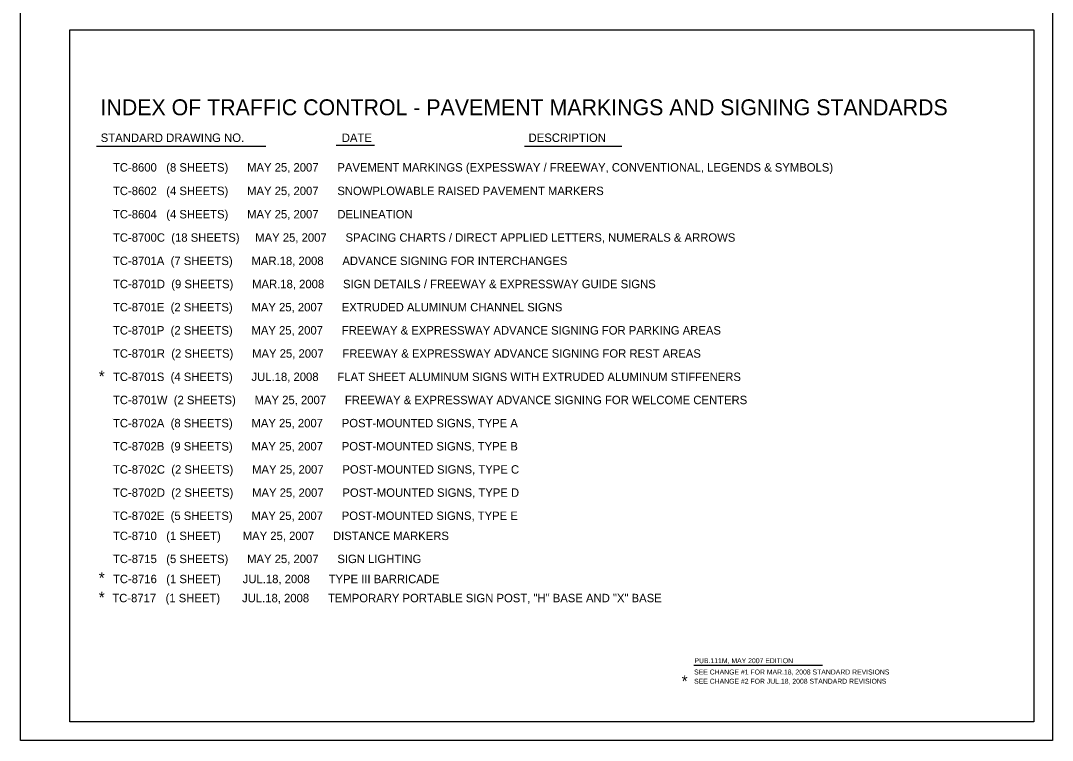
# Model space of a CAD drawing. Extents: x -1746 to -905, y 22 to 1210.
# Drawn here: x -1746 to -905, y 22 to 609 of the extents above; entities that cross this region are included whole.
import ezdxf

# ---------------------------------------------------------------- set-up
doc = ezdxf.new("R2010")
doc.units = 0
for name, color, linetype in [('1', 7, 'Continuous'), ('Level 1', 7, 'Continuous'), ('Level 2', 7, 'Continuous'), ('PLT-BNDY', 7, 'Continuous')]:
    doc.layers.add(name, color=color, linetype=linetype)

msp = doc.modelspace()

# ---------------------------------------------------------------- linework, layer by layer
at = {"layer": '1'}
msp.add_line((-1197.52, 83.48), (-1092.44, 83.48), dxfattribs=at)
at = {"layer": 'Level 1'}
for p, q in [((-1706.14, 601.17), (-920.14, 601.17)), ((-1706.14, 37.17), (-1706.14, 601.17)), ((-920.14, 601.17), (-920.14, 37.17)), ((-920.14, 37.17), (-1706.14, 37.17))]:
    msp.add_line(p, q, dxfattribs=at)
at = {"layer": 'Level 2'}
for p, q in [((-1684.39, 506.28), (-1546.27, 506.28)), ((-1488.89, 507.28), (-1457.77, 507.28)), ((-1335.52, 506.28), (-1256.14, 506.28)), ((-1670.89, 492.53), (-1670.89, 492.53)), ((-1670.89, 454.38), (-1670.89, 454.38)), ((-1670.89, 435.38), (-1670.89, 435.38)), ((-1670.89, 416.5), (-1670.89, 416.5)), ((-1670.89, 359.75), (-1670.89, 359.75)), ((-1670.89, 340.88), (-1670.89, 340.88)), ((-1670.89, 284.25), (-1670.89, 284.25)), ((-1670.89, 265.25), (-1670.89, 265.25)), ((-1670.89, 246.38), (-1670.89, 246.38)), ((-1670.89, 227.5), (-1670.89, 227.5)), ((-1670.89, 208.63), (-1670.89, 208.63)), ((-1670.89, 173.5), (-1670.89, 173.5))]:
    msp.add_line(p, q, dxfattribs=at)
at = {"layer": 'PLT-BNDY'}
msp.add_lwpolyline([(-1746.14, 616.17), (-905.14, 616.17), (-905.14, 22.17), (-1746.14, 22.17)], close=True, dxfattribs=at)

# ---------------------------------------------------------------- texts
at = {"layer": '1'}
for s, height, p in [('*', 9.32, (-1682.48, 314.17)), ('*', 9.32, (-1682.48, 149.9)), ('*', 9.32, (-1682.48, 133.99)), ('PUB.111M, MAY 2007 EDITION', 4.044, (-1196.89, 85.08)), ('SEE CHANGE #1 FOR MAR.18, 2008 STANDARD REVISIONS', 4.044, (-1197.16, 75.85)), ('SEE CHANGE #2 FOR JUL.18, 2008 STANDARD REVISIONS', 4.044, (-1197.16, 68.34))]:
    msp.add_text(s, height=height, dxfattribs=at).set_placement(p)
msp.add_text('*', height=9.32, rotation=360, dxfattribs=at).set_placement((-1207.3, 65.81))
at = {"layer": 'Level 2'}
for s, height, p in [('INDEX OF TRAFFIC CONTROL - PAVEMENT MARKINGS AND SIGNING STANDARDS', 13, (-1681.03, 531.56)), ('STANDARD DRAWING NO.', 6.9067, (-1680.89, 509.78)), ('DATE', 6.907, (-1484.39, 509.78)), ('DESCRIPTION', 6.9067, (-1332.14, 509.78)), ('TC-8600   (8 SHEETS)      MAY 25, 2007      PAVEMENT MARKINGS (EXPESSWAY / FREEWAY, CONVENTIONAL, LEGENDS & SYMBOLS)', 6.87525, (-1670.89, 485.66)), ('TC-8602   (4 SHEETS)      MAY 25, 2007      SNOWPLOWABLE RAISED PAVEMENT MARKERS', 6.8753, (-1670.89, 466.5)), ('TC-8604   (4 SHEETS)      MAY 25, 2007      DELINEATION', 6.8753, (-1670.89, 447.5)), ('TC-8700C  (18 SHEETS)     MAY 25, 2007      SPACING CHARTS / DIRECT APPLIED LETTERS, NUMERALS & ARROWS', 6.87525, (-1670.89, 428.5)), ('TC-8701A  (7 SHEETS)      MAR.18, 2008      ADVANCE SIGNING FOR INTERCHANGES', 6.8753, (-1670.89, 409.5)), ('TC-8701D  (9 SHEETS)      MAR.18, 2008      SIGN DETAILS / FREEWAY & EXPRESSWAY GUIDE SIGNS', 6.8753, (-1670.89, 390.63)), ('TC-8701E  (2 SHEETS)      MAY 25, 2007      EXTRUDED ALUMINUM CHANNEL SIGNS', 6.8753, (-1670.89, 371.75)), ('TC-8701P  (2 SHEETS)      MAY 25, 2007      FREEWAY & EXPRESSWAY ADVANCE SIGNING FOR PARKING AREAS', 6.8753, (-1670.89, 352.88)), ('TC-8701R  (2 SHEETS)      MAY 25, 2007      FREEWAY & EXPRESSWAY ADVANCE SIGNING FOR REST AREAS', 6.8753, (-1670.89, 334)), ('TC-8701S  (4 SHEETS)      JUL.18, 2008      FLAT SHEET ALUMINUM SIGNS WITH EXTRUDED ALUMINUM STIFFENERS', 6.87525, (-1670.89, 315)), ('TC-8701W  (2 SHEETS)      MAY 25, 2007      FREEWAY & EXPRESSWAY ADVANCE SIGNING FOR WELCOME CENTERS', 6.8753, (-1670.89, 296.13)), ('TC-8702A  (8 SHEETS)      MAY 25, 2007      POST-MOUNTED SIGNS, TYPE A', 6.8753, (-1670.89, 277.25)), ('TC-8702B  (9 SHEETS)      MAY 25, 2007      POST-MOUNTED SIGNS, TYPE B', 6.8753, (-1670.89, 258.38)), ('TC-8702C  (2 SHEETS)      MAY 25, 2007      POST-MOUNTED SIGNS, TYPE C', 6.8753, (-1670.89, 239.5)), ('TC-8702D  (2 SHEETS)      MAY 25, 2007      POST-MOUNTED SIGNS, TYPE D', 6.8753, (-1670.89, 220.63)), ('TC-8702E  (5 SHEETS)      MAY 25, 2007      POST-MOUNTED SIGNS, TYPE E', 6.8753, (-1670.89, 201.75)), ('TC-8710   (1 SHEET)       MAY 25, 2007      DISTANCE MARKERS', 6.8753, (-1670.89, 185.38)), ('TC-8715   (5 SHEETS)      MAY 25, 2007      SIGN LIGHTING', 6.8753, (-1670.89, 166.63)), ('TC-8716   (1 SHEET)       JUL.18, 2008      TYPE III BARRICADE', 6.8753, (-1670.89, 150.25)), ('TC-8717   (1 SHEET)       JUL.18, 2008      TEMPORARY PORTABLE SIGN POST, "H" BASE AND "X" BASE', 6.8753, (-1671.43, 134.7))]:
    msp.add_text(s, height=height, dxfattribs=at).set_placement(p)

doc.saveas('drawing.dxf')
